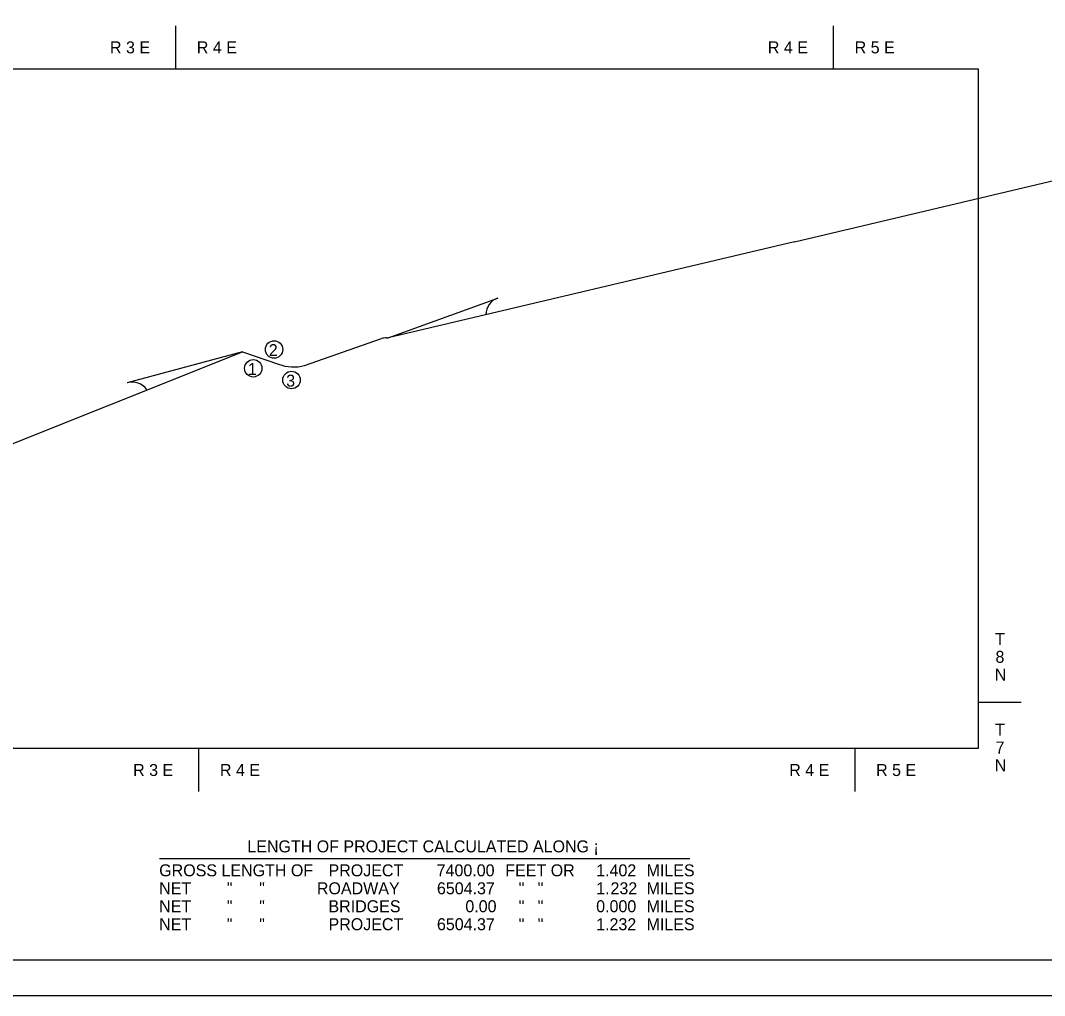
# Model space of a CAD drawing. Extents: x -0.25 to 1.92, y 0 to 0.95.
# Drawn here: x 0.472 to 1.071, y 0 to 0.57 of the extents above; entities that cross this region are included whole.
import ezdxf

# ---------------------------------------------------------------- set-up
doc = ezdxf.new("R2010")
doc.units = 0
for name, color, linetype in [('Default', 7, 'Continuous'), ('DSN_DRFT_DNC', 7, 'Continuous'), ('DSN_DRFT_Guideline-No-Plot', 7, 'Continuous'), ('SHET_Annotations', 7, 'Continuous'), ('SHET_Border-Lines', 7, 'Continuous'), ('SHET_Border-Text', 7, 'Continuous')]:
    doc.layers.add(name, color=color, linetype=linetype)

msp = doc.modelspace()

# ---------------------------------------------------------------- linework, layer by layer
at = {"layer": 'Default'}
for p, q in [((0.92441, 0.44059), (1.1095, 0.48437)), ((0.75105, 0.40768), (0.75113, 0.40768)), ((0.63817, 0.36816), (0.68309, 0.38398)), ((0.68587, 0.38442), (0.68697, 0.38442)), ((0.60176, 0.37631), (0.62291, 0.369)), ((0.53442, 0.3581), (0.53435, 0.35806))]:
    msp.add_line(p, q, dxfattribs=at)
for points in [[(0.92441, 0.44059), (0.68697, 0.38442), (0.75105, 0.40768)], [(0.3699, 0.28371), (0.60176, 0.37631), (0.53442, 0.3581)]]:
    msp.add_lwpolyline(points, dxfattribs=at)
for centre, radius, start, end in [((0.7544, 0.39786), 0.01035, 108.42809, 179.68172), ((0.68714, 0.3675), 0.01696, 94.26275, 103.80525), ((0.63186, 0.39268), 0.02532, 249.29683, 284.43377), ((0.53739, 0.34791), 0.01059, 35.39725, 106.65088)]:
    msp.add_arc(centre, radius, start, end, dxfattribs=at)
at = {"layer": 'DSN_DRFT_DNC'}
msp.add_lwpolyline([(0.38477, 0.54167), (1.0319, 0.54167), (1.0319, 0.1443), (0.38477, 0.1443)], close=True, dxfattribs=at)
at = {"layer": 'DSN_DRFT_Guideline-No-Plot'}
msp.add_lwpolyline([(0, 0), (1.41667, 0), (1.41667, 0.91667), (0, 0.91667)], close=True, dxfattribs=at)
at = {"layer": 'SHET_Annotations'}
for p, q in [((0.56265, 0.56667), (0.56266, 0.54167)), ((0.94718, 0.56667), (0.94718, 0.54167)), ((1.0319, 0.17145), (1.0569, 0.17145)), ((0.57618, 0.1443), (0.57618, 0.1193)), ((0.95968, 0.1443), (0.95968, 0.1193))]:
    msp.add_line(p, q, dxfattribs=at)
for centre in [(0.62032, 0.3776), (0.60814, 0.36659), (0.6305, 0.35975)]:
    msp.add_circle(centre, 0.00509, dxfattribs=at)
at = {"layer": 'SHET_Border-Lines'}
msp.add_lwpolyline([(0.02083, 0.02083), (1.39583, 0.02083), (1.39583, 0.89583), (0.02083, 0.89583)], close=True, dxfattribs=at)
at = {"layer": 'SHET_Border-Text'}
msp.add_line((0.55333, 0.08017), (0.86333, 0.08017), dxfattribs=at)

# ---------------------------------------------------------------- texts
at = {"layer": 'SHET_Annotations'}
for s, p in [('R 3 E', (0.5244, 0.55067)), ('R 4 E', (0.57516, 0.55067)), ('R 4 E', (0.90892, 0.55067)), ('R 5 E', (0.95968, 0.55067)), ('2', (0.61721, 0.37371)), ('1', (0.60502, 0.36271)), ('3', (0.62739, 0.35586)), ('T', (1.04176, 0.20495)), ('8', (1.04196, 0.19445)), ('N', (1.0416, 0.18395)), ('T', (1.04176, 0.15195)), ('7', (1.04203, 0.14145)), ('N', (1.0416, 0.13095)), ('R 3 E', (0.53792, 0.1283)), ('R 4 E', (0.58868, 0.1283)), ('R 4 E', (0.92142, 0.1283)), ('R 5 E', (0.97218, 0.1283)), ('7400.00', (0.71534, 0.06967)), ('1.402 ', (0.80858, 0.06967)), ('MILES', (0.83801, 0.06967)), ('6504.37', (0.71551, 0.05917)), ('1.', (0.80858, 0.05917)), ('232 ', (0.81696, 0.05917)), ('MILES', (0.83801, 0.05917)), ('0.00', (0.73211, 0.04867)), ('0.000 ', (0.80858, 0.04867)), ('MILES', (0.83801, 0.04867)), ('6504.37', (0.71551, 0.03817)), ('1.232 ', (0.80858, 0.03817)), ('MILES', (0.83801, 0.03817))]:
    msp.add_text(s, height=0.007, dxfattribs=at).set_placement(p)
at = {"layer": 'SHET_Border-Text'}
for s, p in [('LENGTH OF PROJECT CALCULATED ALONG ¡', (0.60467, 0.08367)), ('GROSS LENGTH OF', (0.55315, 0.06967)), ('PROJECT', (0.65213, 0.06967)), ('FEET OR', (0.75548, 0.06967)), ('NET        "      "', (0.55315, 0.05917)), ('ROADWAY', (0.64534, 0.05917)), ('   "   "', (0.75548, 0.05917)), ('NET        "      "', (0.55315, 0.04867)), ('BRIDGES', (0.65209, 0.04867)), ('   "   "', (0.75548, 0.04867)), ('NET        "      "', (0.55315, 0.03817)), ('PROJECT', (0.65213, 0.03817)), ('   "   "', (0.75548, 0.03817))]:
    msp.add_text(s, height=0.007, dxfattribs=at).set_placement(p)

doc.saveas('drawing.dxf')
